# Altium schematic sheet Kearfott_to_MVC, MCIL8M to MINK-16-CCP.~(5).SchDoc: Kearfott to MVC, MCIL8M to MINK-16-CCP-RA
size A; Engineer: Hans Thomas; PageSetup: Record=PageOptions|CenterHorizontal=True|CenterVertical=True|PrintScale=1.40|XCorrection=1.00|YCorrection=1.00|PrintKind=0|BorderSize=5000000|LeftOffset=0|BottomOffset=0|Orientation=2|PaperLength=1000|PaperWidth=1000|Scale=100|PaperSource=7|PrintQuality=-4|MediaType=1|DitherType=10|PaperKind=11x17|PrintScaleMode=1
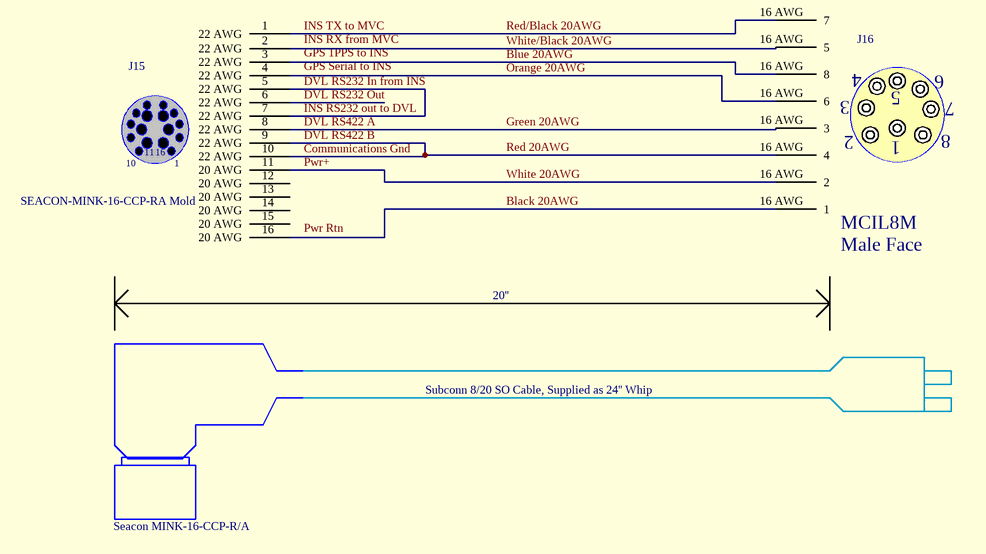
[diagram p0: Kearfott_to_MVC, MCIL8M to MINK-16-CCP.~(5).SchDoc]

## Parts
*  Seacon MINK-16-CCP-R/A
J15  SEACON-MINK-16-CCP-RA Mold
J16  MCIL8M  View: Male Face

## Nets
Black 20AWG: J15.16(20_AWG) J16.16_AWG(1)
Blue 20AWG: J15.3(22_AWG) J16.16_AWG(8)
Communications Gnd: J15.9(22_AWG) J15.10(22_AWG) J16.16_AWG(4)  [also labelled DVL RS422 B, Red 20AWG]
DVL RS232 In from INS: J15.5(22_AWG) J15.7(22_AWG)  [also labelled INS RS232 out to DVL]
DVL RS232 Out: J15.6(22_AWG)
DVL RS422 A: J15.8(22_AWG) J16.16_AWG(3)  [also labelled Green 20AWG]
INS TX to MVC: J15.1(22_AWG) J16.16_AWG(7)  [also labelled Red/Black 20AWG]
Orange 20AWG: J15.4(22_AWG) J16.16_AWG(6)
Pwr+: J15.11(20_AWG) J16.16_AWG(2)  [also labelled White 20AWG]
White/Black 20AWG: J15.2(22_AWG) J16.16_AWG(5)

Not connected (* = marked no-connect by the designer): J15 12(20_AWG) 13(20_AWG) 14(20_AWG) 15(20_AWG)

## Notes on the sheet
- 20''
- Subconn 8/20 SO Cable, Supplied as 24'' Whip
- Labels drawn without touching a wire or pin: GPS 1PPS to INS, GPS Serial to INS, INS RX from MVC, Pwr Rtn

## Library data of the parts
* = CONN-MIN-CCP-RA-LARGE
J15 = SEACON-MINK-16-FCR: Seacon MINK-16 FCR
J16 = SUBCONN-MCxx8M: Subconn MCIL8M Connector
